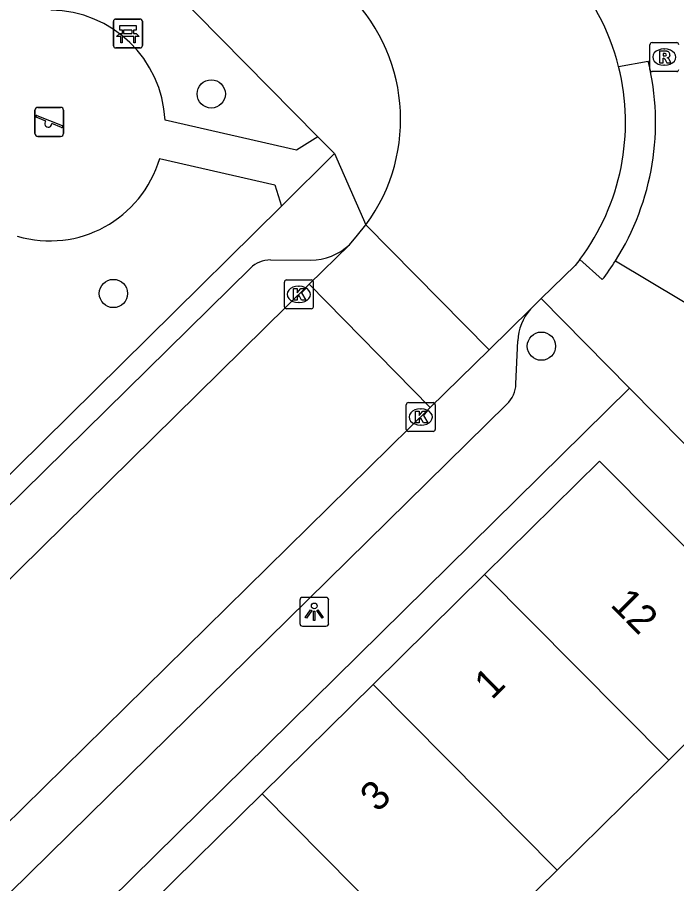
# Model space of a CAD drawing. Extents: x 160107 to 160928, y 382056 to 382918.
# Drawn here: x 160625.81 to 160648.6, y 382634.56 to 382664.5 of the extents above; entities that cross this region are included whole.
import ezdxf

# ---------------------------------------------------------------- set-up
doc = ezdxf.new("R2010")
doc.units = 0
for name, color, linetype in [('IMGEO_Bank', 7, 'Continuous'), ('IMGEO_Boom', 7, 'Continuous'), ('IMGEO_Kolk', 7, 'Continuous'), ('IMGEO_Lichtpunt', 7, 'Continuous'), ('IMGEO_Pand', 7, 'Continuous'), ('IMGEO_Pand_nummerreeks', 7, 'Continuous'), ('IMGEO_Rijbaan_lokaal_open', 7, 'Continuous'), ('IMGEO_Rioolput', 7, 'Continuous'), ('IMGEO_Speelvoorziening', 7, 'Continuous'), ('IMGEO_Voetpad_open', 7, 'Continuous')]:
    doc.layers.add(name, color=color, linetype=linetype)

msp = doc.modelspace()

# ---------------------------------------------------------------- linework, layer by layer
at = {"layer": 'IMGEO_Bank'}
for p, q in [((160629.131, 382663.515), (160629.131, 382664.356)), ((160629.131, 382664.356), (160629.131, 382663.515)), ((160629.206, 382664.44), (160630.047, 382664.44)), ((160630.047, 382664.44), (160629.206, 382664.44)), ((160630.131, 382664.365), (160630.131, 382663.524)), ((160630.131, 382663.524), (160630.131, 382664.365)), ((160629.44, 382663.946), (160629.44, 382664.052)), ((160629.484, 382664.052), (160629.484, 382663.946)), ((160629.772, 382664.058), (160629.49, 382664.058)), ((160629.49, 382663.94), (160629.772, 382663.94)), ((160629.778, 382663.946), (160629.778, 382664.052)), ((160629.822, 382664.052), (160629.822, 382663.946)), ((160629.828, 382663.838), (160629.435, 382663.838)), ((160630.056, 382663.44), (160629.215, 382663.44)), ((160629.215, 382663.44), (160630.056, 382663.44))]:
    msp.add_line(p, q, dxfattribs=at)
for points in [[(160629.434, 382664.058), (160629.348, 382664.058), (160629.348, 382664.219), (160629.911, 382664.219), (160629.911, 382664.058), (160629.828, 382664.058)], [(160629.378, 382663.838), (160629.236, 382663.838), (160629.348, 382663.94), (160629.434, 382663.94)], [(160629.828, 382663.94), (160629.911, 382663.94), (160630.023, 382663.838), (160629.884, 382663.838)], [(160629.428, 382663.831), (160629.428, 382663.624), (160629.385, 382663.624), (160629.385, 382663.831)], [(160629.878, 382663.831), (160629.878, 382663.624), (160629.834, 382663.624), (160629.834, 382663.831)]]:
    msp.add_lwpolyline(points, dxfattribs=at)
for centre, radius, start, end in [((160629.209, 382664.362), 0.0779, 92.4484, 184.2845), ((160629.209, 382664.362), 0.0779, 92.4484, 184.2845), ((160630.053, 382664.362), 0.0779, 2.4484, 94.2845), ((160630.053, 382664.362), 0.0779, 2.4484, 94.2845), ((160629.433, 382664.051), 0.00671, 2.8957, 87.1043), ((160629.433, 382663.947), 0.00671, 272.8957, 357.1043), ((160629.49, 382664.051), 0.00671, 92.8957, 177.1043), ((160629.49, 382663.947), 0.00671, 182.8957, 267.1043), ((160629.772, 382664.051), 0.00671, 2.8957, 87.1043), ((160629.772, 382663.947), 0.00671, 272.8957, 357.1043), ((160629.829, 382664.051), 0.00671, 92.8957, 177.1043), ((160629.829, 382663.947), 0.00671, 182.8957, 267.1043), ((160629.378, 382663.831), 0.00671, 2.8957, 87.1043), ((160629.435, 382663.831), 0.00671, 92.8957, 177.1043), ((160629.827, 382663.831), 0.00671, 2.8957, 87.1043), ((160629.884, 382663.831), 0.00671, 92.8957, 177.1043), ((160629.209, 382663.518), 0.0779, 182.4484, 274.2845), ((160629.209, 382663.518), 0.0779, 182.4484, 274.2845), ((160630.053, 382663.518), 0.0779, 272.4484, 4.2845), ((160630.053, 382663.518), 0.0779, 272.4484, 4.2845)]:
    msp.add_arc(centre, radius, start, end, dxfattribs=at)
at = {"layer": 'IMGEO_Boom'}
for centre in [(160632.511, 382661.853), (160629.13, 382654.956), (160643.924, 382653.135)]:
    msp.add_circle(centre, 0.489, dxfattribs=at)
at = {"layer": 'IMGEO_Kolk'}
for p, q in [((160635.039, 382654.5), (160635.039, 382655.352)), ((160635.114, 382655.426), (160635.966, 382655.426)), ((160635.527, 382655.206), (160635.552, 382655.206)), ((160636.04, 382655.352), (160636.04, 382654.5)), ((160635.55, 382654.646), (160635.525, 382654.646)), ((160635.966, 382654.426), (160635.114, 382654.426)), ((160639.253, 382650.261), (160639.253, 382651.113)), ((160639.328, 382651.187), (160640.18, 382651.187)), ((160640.254, 382651.113), (160640.254, 382650.261)), ((160639.741, 382650.967), (160639.766, 382650.967)), ((160639.764, 382650.407), (160639.739, 382650.407)), ((160640.18, 382650.187), (160639.328, 382650.187))]:
    msp.add_line(p, q, dxfattribs=at)
for points in [[(160635.039, 382654.5), (160635.039, 382655.352)], [(160635.114, 382655.426), (160635.966, 382655.426)], [(160636.04, 382655.352), (160636.04, 382654.5)], [(160635.36, 382655.126), (160635.483, 382655.126), (160635.483, 382654.975), (160635.613, 382655.126), (160635.777, 382655.126), (160635.631, 382654.975), (160635.784, 382654.726), (160635.632, 382654.726), (160635.547, 382654.89), (160635.483, 382654.823), (160635.483, 382654.726), (160635.36, 382654.726), (160635.36, 382655.126)], [(160635.966, 382654.426), (160635.114, 382654.426)], [(160639.253, 382650.261), (160639.253, 382651.113)], [(160639.328, 382651.187), (160640.18, 382651.187)], [(160640.254, 382651.113), (160640.254, 382650.261)], [(160639.574, 382650.887), (160639.697, 382650.887), (160639.697, 382650.736), (160639.827, 382650.887), (160639.991, 382650.887), (160639.845, 382650.736), (160639.998, 382650.487), (160639.846, 382650.487), (160639.761, 382650.651), (160639.697, 382650.584), (160639.697, 382650.487), (160639.574, 382650.487), (160639.574, 382650.887)], [(160640.18, 382650.187), (160639.328, 382650.187)]]:
    msp.add_lwpolyline(points, dxfattribs=at)
for centre, start, end in [((160635.116, 382655.35), 91.552, 178.448), ((160635.116, 382655.35), 91.552, 178.448), ((160635.964, 382655.35), 1.552, 88.448), ((160635.964, 382655.35), 1.552, 88.448), ((160635.116, 382654.502), 181.552, 268.448), ((160635.116, 382654.502), 181.552, 268.448), ((160635.964, 382654.502), 271.552, 358.448), ((160635.964, 382654.502), 271.552, 358.448), ((160639.33, 382651.111), 91.552, 178.448), ((160639.33, 382651.111), 91.552, 178.448), ((160640.178, 382651.111), 1.552, 88.448), ((160640.178, 382651.111), 1.552, 88.448), ((160639.33, 382650.263), 181.552, 268.448), ((160639.33, 382650.263), 181.552, 268.448), ((160640.178, 382650.263), 271.552, 358.448), ((160640.178, 382650.263), 271.552, 358.448)]:
    msp.add_arc(centre, 0.0765, start, end, dxfattribs=at)
for centre, major_axis, ratio, start_param, end_param in [((160635.526, 382654.926), (-0.387, 0.002), 0.722429, 4.712389, 7.853982), ((160635.551, 382654.926), (-0.39, 0.002), 0.717154, 1.570796, 4.712389), ((160639.74, 382650.687), (-0.387, 0.002), 0.722429, 4.712389, 7.853982), ((160639.765, 382650.687), (-0.39, 0.002), 0.717154, 1.570796, 4.712389)]:
    msp.add_ellipse(centre, major_axis=major_axis, ratio=ratio, start_param=start_param, end_param=end_param, dxfattribs=at)
at = {"layer": 'IMGEO_Lichtpunt'}
for p, q in [((160636.476, 382644.455), (160635.668, 382644.455)), ((160636.476, 382644.455), (160635.668, 382644.455)), ((160635.574, 382644.36), (160635.574, 382643.553)), ((160635.574, 382644.36), (160635.574, 382643.553)), ((160636.57, 382643.553), (160636.57, 382644.36)), ((160636.57, 382643.553), (160636.57, 382644.36)), ((160635.668, 382643.459), (160636.476, 382643.459)), ((160635.668, 382643.459), (160636.476, 382643.459))]:
    msp.add_line(p, q, dxfattribs=at)
for points in [[(160635.948, 382644.024), (160635.987, 382643.996), (160635.799, 382643.734), (160635.761, 382643.761), (160635.948, 382644.024)], [(160636.05, 382643.976), (160636.097, 382643.976), (160636.097, 382643.654), (160636.05, 382643.654), (160636.05, 382643.976)], [(160636.16, 382643.996), (160636.198, 382644.023), (160636.385, 382643.761), (160636.346, 382643.733), (160636.16, 382643.996)]]:
    msp.add_lwpolyline(points, dxfattribs=at)
msp.add_circle((160636.073, 382644.158), 0.0994, dxfattribs=at)
for centre, start, end in [((160635.668, 382644.36), 90, 180), ((160635.668, 382644.36), 90, 180), ((160636.476, 382644.36), 0, 90), ((160636.476, 382644.36), 0, 90), ((160635.668, 382643.553), 180, 270), ((160635.668, 382643.553), 180, 270), ((160636.476, 382643.553), 270, 0), ((160636.476, 382643.553), 270, 360)]:
    msp.add_arc(centre, 0.0946, start, end, dxfattribs=at)
at = {"layer": 'IMGEO_Pand'}
for points in [[(160648.326, 382638.824), (160648.748, 382639.239), (160652.312, 382642.745), (160645.935, 382649.166), (160641.954, 382645.241)], [(160641.954, 382645.241), (160638.105, 382641.447)], [(160641.954, 382645.241), (160648.326, 382638.824)], [(160638.105, 382641.447), (160634.268, 382637.664)], [(160644.465, 382635.025), (160638.105, 382641.447)], [(160644.465, 382635.025), (160648.326, 382638.824)], [(160634.268, 382637.664), (160630.432, 382633.883)], [(160634.268, 382637.664), (160640.62, 382631.244)], [(160640.62, 382631.244), (160644.465, 382635.025)]]:
    msp.add_lwpolyline(points, dxfattribs=at)
at = {"layer": 'IMGEO_Rijbaan_lokaal_open'}
for points in [[(160637.287, 382656.637), (160637.564, 382656.967), (160637.855, 382657.329)], [(160637.855, 382657.329), (160642.116, 382653.012)], [(160635.901, 382655.273), (160637.287, 382656.637)], [(160645.257, 382656.136), (160645.09, 382655.921), (160643.916, 382654.779)], [(160635.901, 382655.273), (160607.381, 382627.202), (160605.252, 382625.176)], [(160640.083, 382651.015), (160635.901, 382655.273)], [(160643.543, 382654.414), (160643.916, 382654.779)], [(160642.116, 382653.012), (160643.543, 382654.414)], [(160642.116, 382653.012), (160640.083, 382651.015)], [(160621.788, 382633.043), (160640.083, 382651.015)]]:
    msp.add_lwpolyline(points, dxfattribs=at)
for centre, radius, start, end in [((160638.93, 382660.859), 7.903, 14.1848, 42.1525), ((160632.95, 382660.969), 6.108, 323.4229, 47.1606), ((160638.923, 382660.869), 7.907, 323.2285, 14.102)]:
    msp.add_arc(centre, radius, start, end, dxfattribs=at)
at = {"layer": 'IMGEO_Rioolput'}
for p, q in [((160647.673, 382662.701), (160647.673, 382663.553)), ((160647.748, 382663.627), (160648.6, 382663.627)), ((160648.161, 382663.407), (160648.186, 382663.407)), ((160648.184, 382662.847), (160648.159, 382662.847)), ((160648.6, 382662.627), (160647.748, 382662.627))]:
    msp.add_line(p, q, dxfattribs=at)
for points in [[(160647.673, 382662.701), (160647.673, 382663.553)], [(160647.748, 382663.627), (160648.6, 382663.627)], [(160648.262, 382663.325), (160648.01, 382663.327), (160648.01, 382662.927)], [(160648.188, 382663.246), (160648.134, 382663.246), (160648.134, 382663.165)], [(160648.01, 382662.927), (160648.134, 382662.927), (160648.134, 382663.089), (160648.145, 382663.089)], [(160648.134, 382663.165), (160648.186, 382663.165)], [(160648.192, 382663.06), (160648.263, 382662.927), (160648.403, 382662.927), (160648.338, 382663.053)], [(160648.6, 382662.627), (160647.748, 382662.627)]]:
    msp.add_lwpolyline(points, dxfattribs=at)
for centre, radius, start, end in [((160647.75, 382663.551), 0.0765, 91.552, 178.448), ((160647.75, 382663.551), 0.0765, 91.552, 178.448), ((160648.598, 382663.551), 0.0765, 1.552, 88.448), ((160648.598, 382663.551), 0.0765, 1.552, 88.448), ((160648.194, 382663.15), 0.0964, 77.0061, 93.1865), ((160648.208, 382663.207), 0.0378, 276.6634, 79.6772), ((160648.261, 382663.215), 0.109, 350.3612, 89.416), ((160648.144, 382663.036), 0.0533, 26.0293, 88.6989), ((160648.17, 382663.354), 0.19, 274.7715, 282.9687), ((160648.259, 382663.215), 0.112, 277.5842, 350.9817), ((160648.243, 382663), 0.108, 29.5134, 73.7905), ((160647.75, 382662.703), 0.0765, 181.552, 268.448), ((160647.75, 382662.703), 0.0765, 181.552, 268.448), ((160648.598, 382662.703), 0.0765, 271.552, 358.448), ((160648.598, 382662.703), 0.0765, 271.552, 358.448)]:
    msp.add_arc(centre, radius, start, end, dxfattribs=at)
for centre, major_axis, ratio, start_param, end_param in [((160648.16, 382663.127), (-0.387, 0.002), 0.722429, 4.712389, 7.853982), ((160648.185, 382663.127), (-0.39, 0.002), 0.717154, 1.570796, 4.712389)]:
    msp.add_ellipse(centre, major_axis=major_axis, ratio=ratio, start_param=start_param, end_param=end_param, dxfattribs=at)
at = {"layer": 'IMGEO_Speelvoorziening'}
for p, q in [((160626.416, 382660.486), (160626.416, 382661.286)), ((160626.416, 382661.286), (160626.416, 382660.486)), ((160626.516, 382661.386), (160627.306, 382661.386)), ((160627.306, 382661.386), (160626.516, 382661.386)), ((160627.406, 382661.286), (160627.406, 382660.486)), ((160627.406, 382660.486), (160627.406, 382661.286)), ((160626.799, 382660.914), (160626.46, 382661.051)), ((160626.485, 382661.111), (160627.361, 382660.758)), ((160627.337, 382660.698), (160626.997, 382660.835)), ((160627.306, 382660.386), (160626.516, 382660.386)), ((160626.516, 382660.386), (160627.306, 382660.386))]:
    msp.add_line(p, q, dxfattribs=at)
for centre, radius, start, end in [((160626.516, 382661.286), 0.1, 90, 180), ((160626.516, 382661.286), 0.1, 90, 180), ((160627.306, 382661.286), 0.1, 0, 90), ((160627.306, 382661.286), 0.1, 360, 90), ((160626.473, 382661.081), 0.0327, 68.078, 248.078), ((160626.878, 382660.824), 0.12, 130.9928, 5.1632), ((160627.349, 382660.728), 0.0327, 248.078, 68.078), ((160626.516, 382660.486), 0.1, 180, 270), ((160626.516, 382660.486), 0.1, 180, 270), ((160627.306, 382660.486), 0.1, 270, 0), ((160627.306, 382660.486), 0.1, 270, 0)]:
    msp.add_arc(centre, radius, start, end, dxfattribs=at)
at = {"layer": 'IMGEO_Voetpad_open'}
for points in [[(160627.418, 382669.217), (160627.794, 382668.892), (160636.199, 382660.37)], [(160646.592, 382662.796), (160647.616, 382662.987)], [(160636.199, 382660.37), (160635.461, 382659.912), (160630.916, 382660.948)], [(160636.77, 382659.791), (160636.199, 382660.37)], [(160634.935, 382657.976), (160636.77, 382659.791)], [(160636.77, 382659.791), (160637.855, 382657.329)], [(160630.728, 382659.622), (160634.71, 382658.712), (160634.935, 382657.976)], [(160634.935, 382657.976), (160630.324, 382653.415), (160619.427, 382642.677)], [(160634.561, 382656.117), (160635.949, 382656.111)], [(160646.03, 382655.434), (160645.257, 382656.136)], [(160646.486, 382656.089), (160649.899, 382654.041)], [(160606.041, 382628.472), (160633.864, 382655.834)], [(160643.916, 382654.779), (160646.97, 382651.686)], [(160643.045, 382651.834), (160643.104, 382653.32)], [(160646.97, 382651.686), (160602.42, 382607.815), (160569.084, 382609.884)], [(160646.97, 382651.686), (160661.762, 382636.708)], [(160624.837, 382633.553), (160642.731, 382651.127)]]:
    msp.add_lwpolyline(points, dxfattribs=at)
for centre, radius, start, end in [((160626.919, 382660.749), 4.002, 2.8449, 89.2695), ((160638.92, 382660.87), 8.95, 327.7114, 13.6819), ((160626.921, 382660.743), 3.969, 253.7187, 343.5985), ((160635.955, 382658.06), 1.949, 269.8159, 313.106), ((160634.559, 382655.122), 0.995, 89.8927, 134.3041), ((160638.909, 382660.878), 8.963, 322.6033, 327.7067), ((160644.933, 382653.221), 1.832, 139.3689, 176.9019), ((160641.988, 382651.88), 1.058, 314.618, 357.4871)]:
    msp.add_arc(centre, radius, start, end, dxfattribs=at)

# ---------------------------------------------------------------- texts
at = {"layer": 'IMGEO_Pand_nummerreeks'}
for s, rotation, p in [('12', 314.803, (160646.276, 382644.168)), ('1', 44.591, (160642.209, 382640.886)), ('3', 44.591, (160638.262, 382636.995))]:
    msp.add_text(s, height=1, rotation=rotation, dxfattribs=at).set_placement(p)

doc.saveas('drawing.dxf')
